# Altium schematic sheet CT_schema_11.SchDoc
size 147 x 119 mm
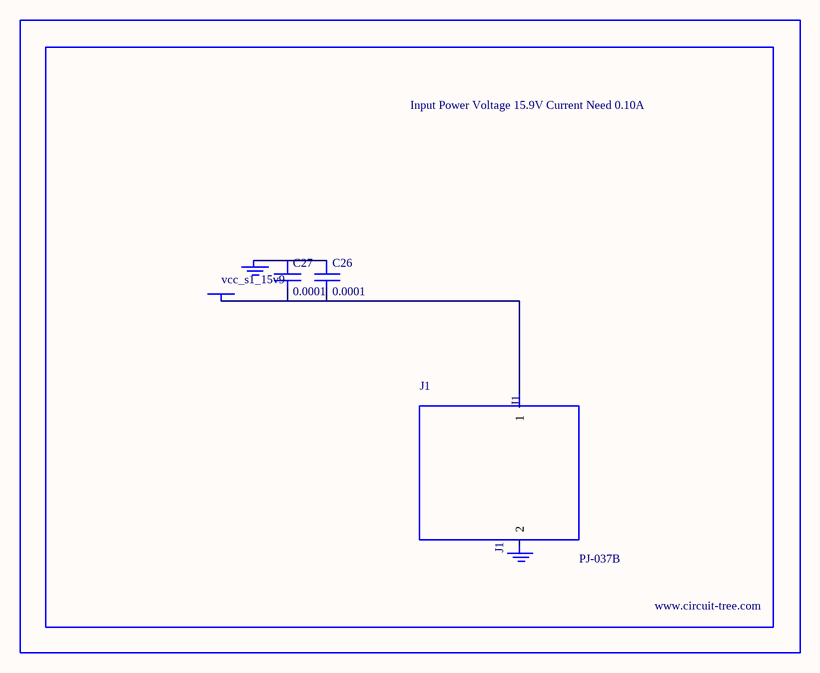
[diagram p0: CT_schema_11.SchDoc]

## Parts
BORDER10  (no value)
C26  0.0001  [EXV-9H]
C27  0.0001  [EXV-9H]
GND_INSTANCE_10_0  (no value)
GND_INSTANCE_10_1  (no value)
J1  PJ-037B  [PJ-037B_PACKAGE]
POWER_INSTANCE_10_0  vcc_s1_15v9

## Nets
NetC26_1: C26.1 C27.1 GND_INSTANCE_10_0.0(GND)
NetC26_2: C26.2 C27.2 J1.1 POWER_INSTANCE_10_0.0(PWR)

Not connected (* = marked no-connect by the designer): GND_INSTANCE_10_1 0(GND); J1 2

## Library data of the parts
BORDER10 = BORDER_PAGE10
C26 C27 = EDK107M035A9HAA
GND_INSTANCE_10_0 GND_INSTANCE_10_1 = GND
POWER_INSTANCE_10_0 = PWR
